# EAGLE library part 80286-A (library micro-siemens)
MICROPROCESSOR/PERIPHERAL DEVICE
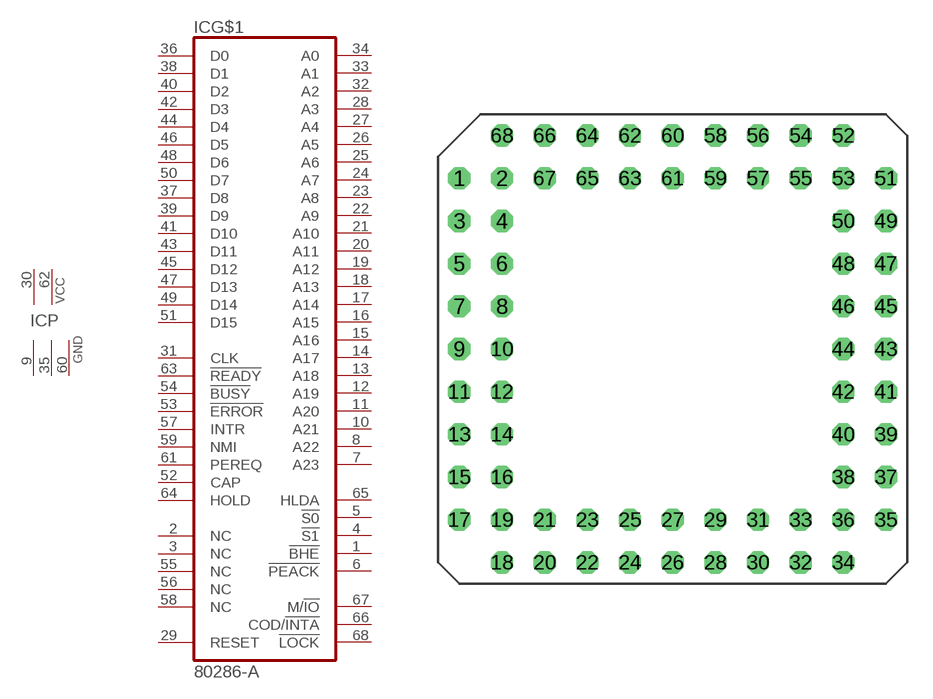
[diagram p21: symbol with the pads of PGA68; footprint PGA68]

Designator prefix IC; gates G$1=80286 P=2VCC3GND

## 80286-A (OC_FARNELL: unknown; OC_NEWARK: unknown)  [PGA68]
1  G$1:!BHE  out
2  G$1:NC  nc
3  G$1:NC  nc
4  G$1:!S1  out
5  G$1:!S0  out
6  G$1:!PEACK  out
7  G$1:A23  out
8  G$1:A22  out
9  P:GND  pwr
10  G$1:A21  out
11  G$1:A20  out
12  G$1:A19  out
13  G$1:A18  out
14  G$1:A17  out
15  G$1:A16  out
16  G$1:A15  out
17  G$1:A14  out
18  G$1:A13  out
19  G$1:A12  out
20  G$1:A11  out
21  G$1:A10  out
22  G$1:A9  out
23  G$1:A8  out
24  G$1:A7  out
25  G$1:A6  out
26  G$1:A5  out
27  G$1:A4  out
28  G$1:A3  out
29  G$1:RESET  in
30  P:VCC  pwr
31  G$1:CLK  in
32  G$1:A2  out
33  G$1:A1  out
34  G$1:A0  out
35  P:GND  pwr
36  G$1:D0
37  G$1:D8
38  G$1:D1
39  G$1:D9
40  G$1:D2
41  G$1:D10
42  G$1:D3
43  G$1:D11
44  G$1:D4
45  G$1:D12
46  G$1:D5
47  G$1:D13
48  G$1:D6
49  G$1:D14
50  G$1:D7
51  G$1:D15
52  G$1:CAP  in
53  G$1:!ERROR  in
54  G$1:!BUSY  in
55  G$1:NC  nc
56  G$1:NC  nc
57  G$1:INTR  in
58  G$1:NC  nc
59  G$1:NMI  in
60  P:GND  pwr
61  G$1:PEREQ  in
62  P:VCC  pwr
63  G$1:!READY  in
64  G$1:HOLD  in
65  G$1:HLDA  out
66  G$1:COD/!INTA  out
67  G$1:M/!IO  out
68  G$1:!LOCK  out

## Footprint PGA68 (pad centres in mm)
Pin Grid Array
drill 0.813 octagon: 1 -12.7,10.16; 2 -10.16,10.16; 3 -12.7,7.62; 4 -10.16,7.62; 5 -12.7,5.08; 6 -10.16,5.08; 7 -12.7,2.54; 8 -10.16,2.54; 9 -12.7,0; 10 -10.16,0; 11 -12.7,-2.54; 12 -10.16,-2.54; 13 -12.7,-5.08; 14 -10.16,-5.08; 15 -12.7,-7.62; 16 -10.16,-7.62; 17 -12.7,-10.16; 18 -10.16,-12.7; 19 -10.16,-10.16; 20 -7.62,-12.7; 21 -7.62,-10.16; 22 -5.08,-12.7; 23 -5.08,-10.16; 24 -2.54,-12.7; 25 -2.54,-10.16; 26 0,-12.7; 27 0,-10.16; 28 2.54,-12.7; 29 2.54,-10.16; 30 5.08,-12.7; 31 5.08,-10.16; 32 7.62,-12.7; 33 7.62,-10.16; 34 10.16,-12.7; 35 12.7,-10.16; 36 10.16,-10.16; 37 12.7,-7.62; 38 10.16,-7.62; 39 12.7,-5.08; 40 10.16,-5.08; 41 12.7,-2.54; 42 10.16,-2.54; 43 12.7,0; 44 10.16,0; 45 12.7,2.54; 46 10.16,2.54; 47 12.7,5.08; 48 10.16,5.08; 49 12.7,7.62; 50 10.16,7.62; 51 12.7,10.16; 52 10.16,12.7; 53 10.16,10.16; 54 7.62,12.7; 55 7.62,10.16; 56 5.08,12.7; 57 5.08,10.16; 58 2.54,12.7; 59 2.54,10.16; 60 0,12.7; 61 0,10.16; 62 -2.54,12.7; 63 -2.54,10.16; 64 -5.08,12.7; 65 -5.08,10.16; 66 -7.62,12.7; 67 -7.62,10.16; 68 -10.16,12.7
